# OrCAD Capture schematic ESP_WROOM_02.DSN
size A3; title: ESP-WROOM-02; rev: 1.0
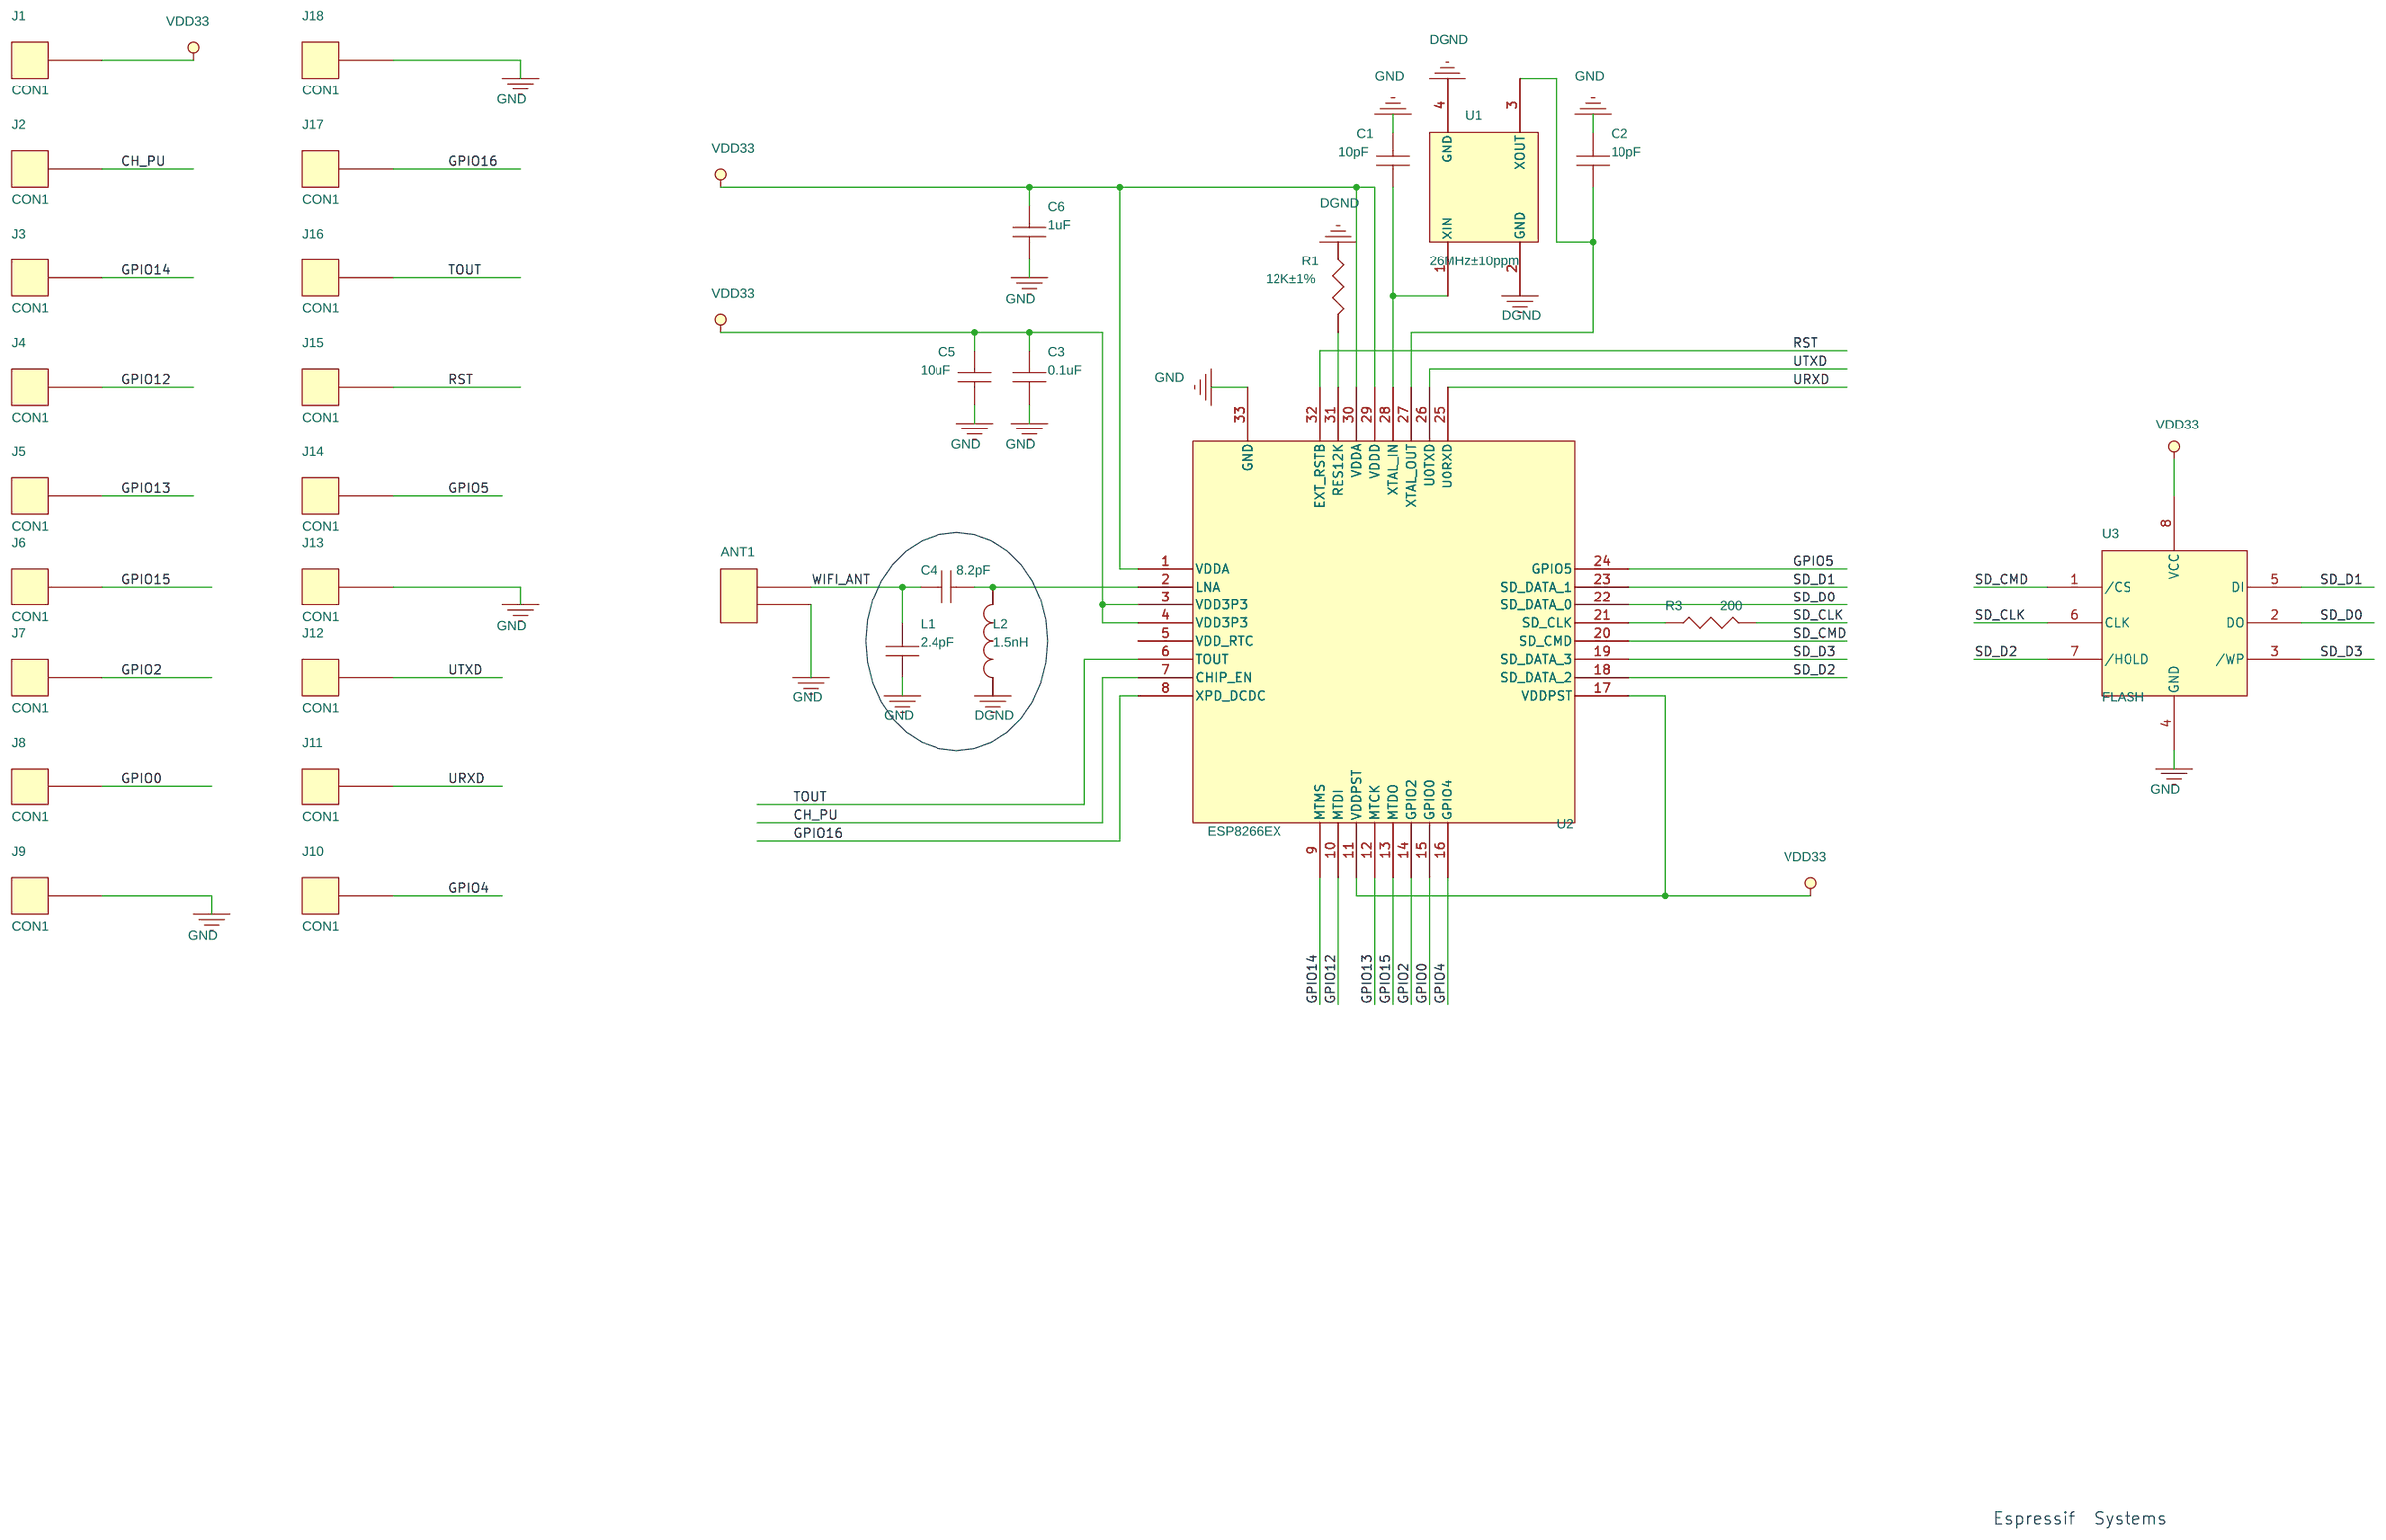
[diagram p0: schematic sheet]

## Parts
ANT1  ANT1  [ANT_DIP2]
C1  10pF  [0402A]
C2  10pF  [0402A]
C3  0.1uF  [0402A]
C4  8.2pF  [0402A]
C5  10uF  [0603C]
C6  1uF  [0603C]
J1  CON1  [SPAD]
J2  CON1  [SPAD]
J3  CON1  [SPAD]
J4  CON1  [SPAD]
J5  CON1  [SPAD]
J6  CON1  [SPAD]
J7  CON1  [SPAD]
J8  CON1  [SPAD]
J9  CON1  [SPAD]
J10  CON1  [SPAD]
J11  CON1  [SPAD]
J12  CON1  [SPAD]
J13  CON1  [SPAD]
J14  CON1  [SPAD]
J15  CON1  [SPAD]
J16  CON1  [SPAD]
J17  CON1  [SPAD]
J18  CON1  [SPAD]
L1  2.4pF  [0402A]
L2  1.5nH  [L0402//A]
R1  12K±1%  [0402A]
R3  200  [0402A]
U1  26MHz±10ppm  [3225]
U2  ESP8266EX  [QFN32_3.7X3.7]
U3  FLASH  [SON-8N]

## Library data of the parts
ANT1 = CON2
C1-C6 L1 = CAP_NP
J1-J18 = CON1
L2 = INDUCTOR
R1 R3 = RESISTOR
U1 = X1_0
U2 = ESP8080_1
U3 = FLASH_1

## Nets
GND: ANT1.2 C1.2 C2.2 C3.2 C5.2 C6.2 J9.1 J13.1 J18.1 L1.1 L2.1 R1.1 U1.2(GND) U1.4(GND) U2.33(GND) U3.4(GND)
VDD33: C3.1 C5.1 C6.1 J1.1 U2.1(VDDA) U2.3(VDD3P3) U2.4(VDD3P3) U2.11(VDDPST) U2.17(VDDPST) U2.29(VDDD) U2.30(VDDA) U3.8(VCC)
VDD_RTC: U2.5(VDD_RTC)
CH_PU: J2.1 U2.7(CHIP_EN)
GPIO0: J8.1 U2.15(GPIO0)
GPIO2: J7.1 U2.14(GPIO2)
GPIO4: J10.1 U2.16(GPIO4)
GPIO5: J14.1 U2.24(GPIO5)
GPIO12: J4.1 U2.10(MTDI)
GPIO13: J5.1 U2.12(MTCK)
GPIO14: J3.1 U2.9(MTMS)
GPIO15: J6.1 U2.13(MTDO)
GPIO16: J17.1 U2.8(XPD_DCDC)
RST: J15.1 U2.32(EXT_RSTB)
SD_CLK: R3.2 U3.6(CLK)
SD_CMD: U2.20(SD_CMD) U3.1(/CS)
SD_D0: U2.22(SD_DATA_0) U3.2(DO)
SD_D1: U2.23(SD_DATA_1) U3.5(DI)
SD_D2: U2.18(SD_DATA_2) U3.7(/HOLD)
SD_D3: U2.19(SD_DATA_3) U3.3(/WP)
TOUT: J16.1 U2.6(TOUT)
URXD: J11.1 U2.25(U0RXD)
UTXD: J12.1 U2.26(U0TXD)
WIFI_ANT: ANT1.1 C4.1 L1.2
N5630608: C2.1 U1.3(XOUT) U2.27(XTAL_OUT)
N5630644: C4.2 L2.2 U2.2(LNA)
N5630726: C1.1 U1.1(XIN) U2.28(XTAL_IN)
N5630864: R1.2 U2.31(RES12K)
N5777066: R3.1 U2.21(SD_CLK)

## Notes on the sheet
- Espressif  Systems
